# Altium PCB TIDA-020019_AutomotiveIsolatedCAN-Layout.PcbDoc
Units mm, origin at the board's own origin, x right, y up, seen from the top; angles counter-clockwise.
Board outline 60 x 40 mm, 2 copper layers (Top Layer, Bottom Layer), stack 1.575 mm thick; 61 components, 26 nets, 143 pads, 64 vias.
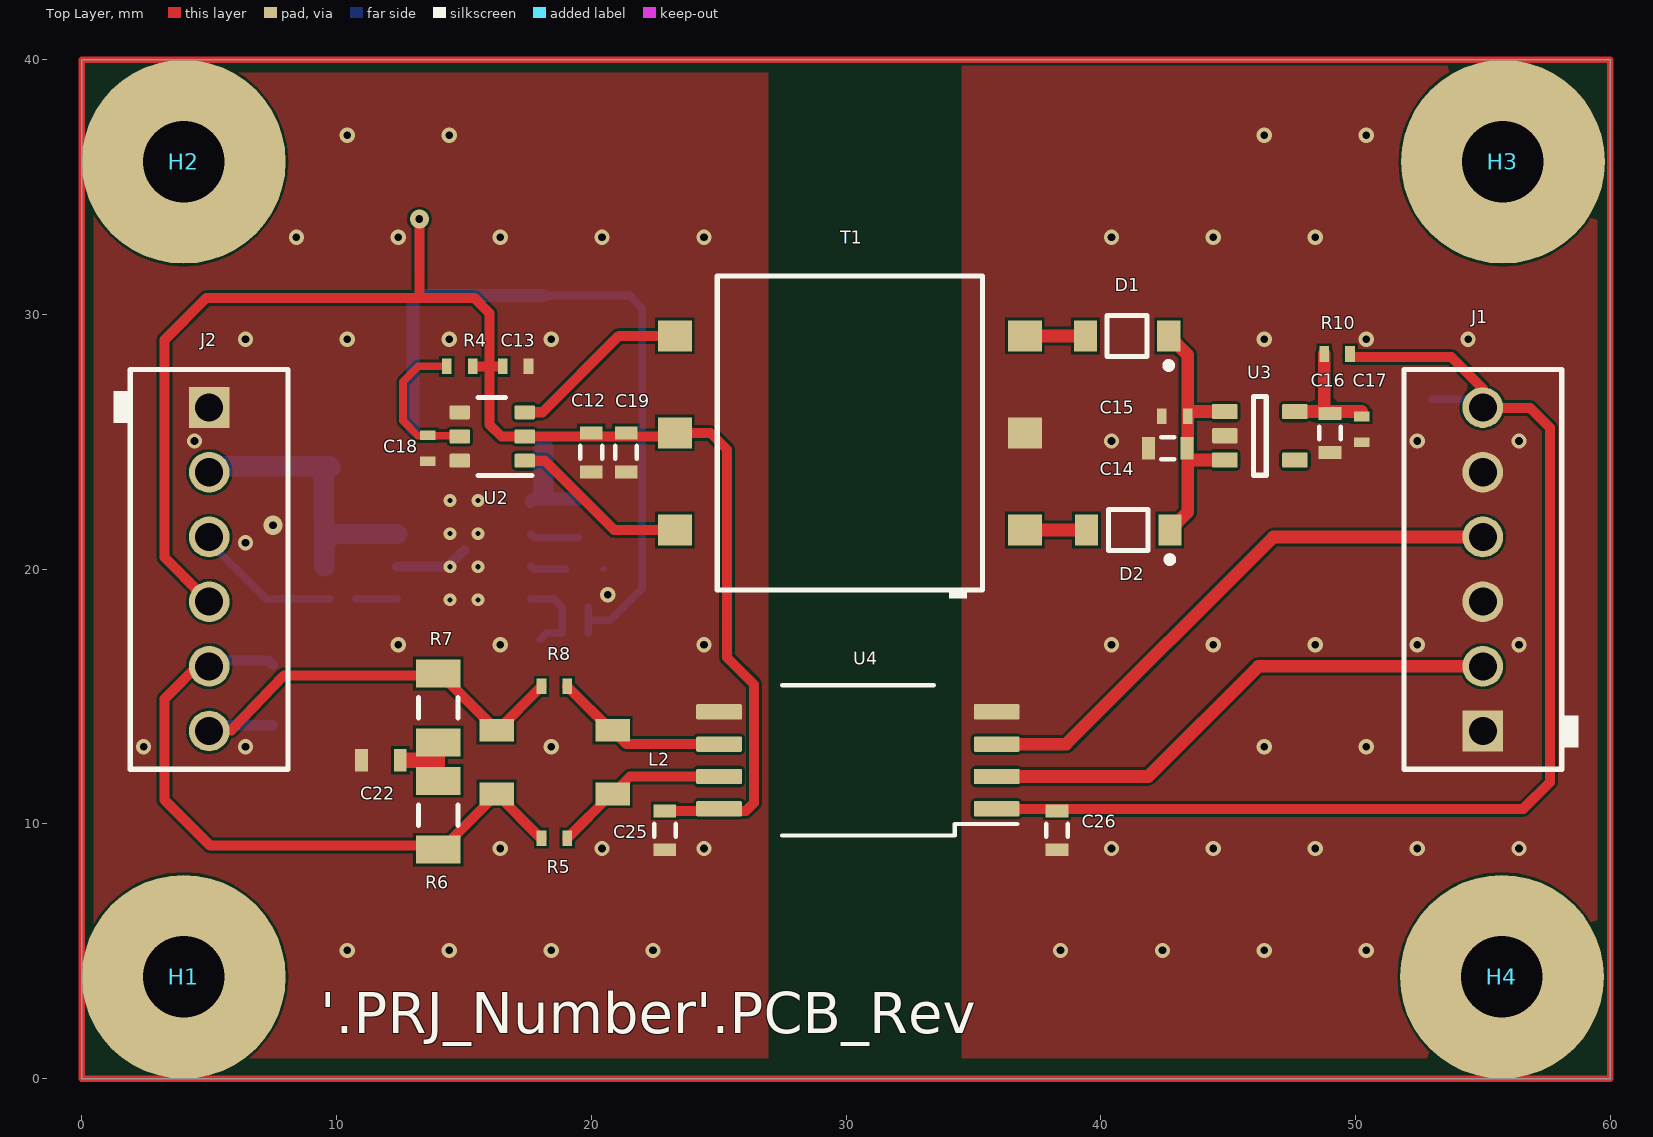
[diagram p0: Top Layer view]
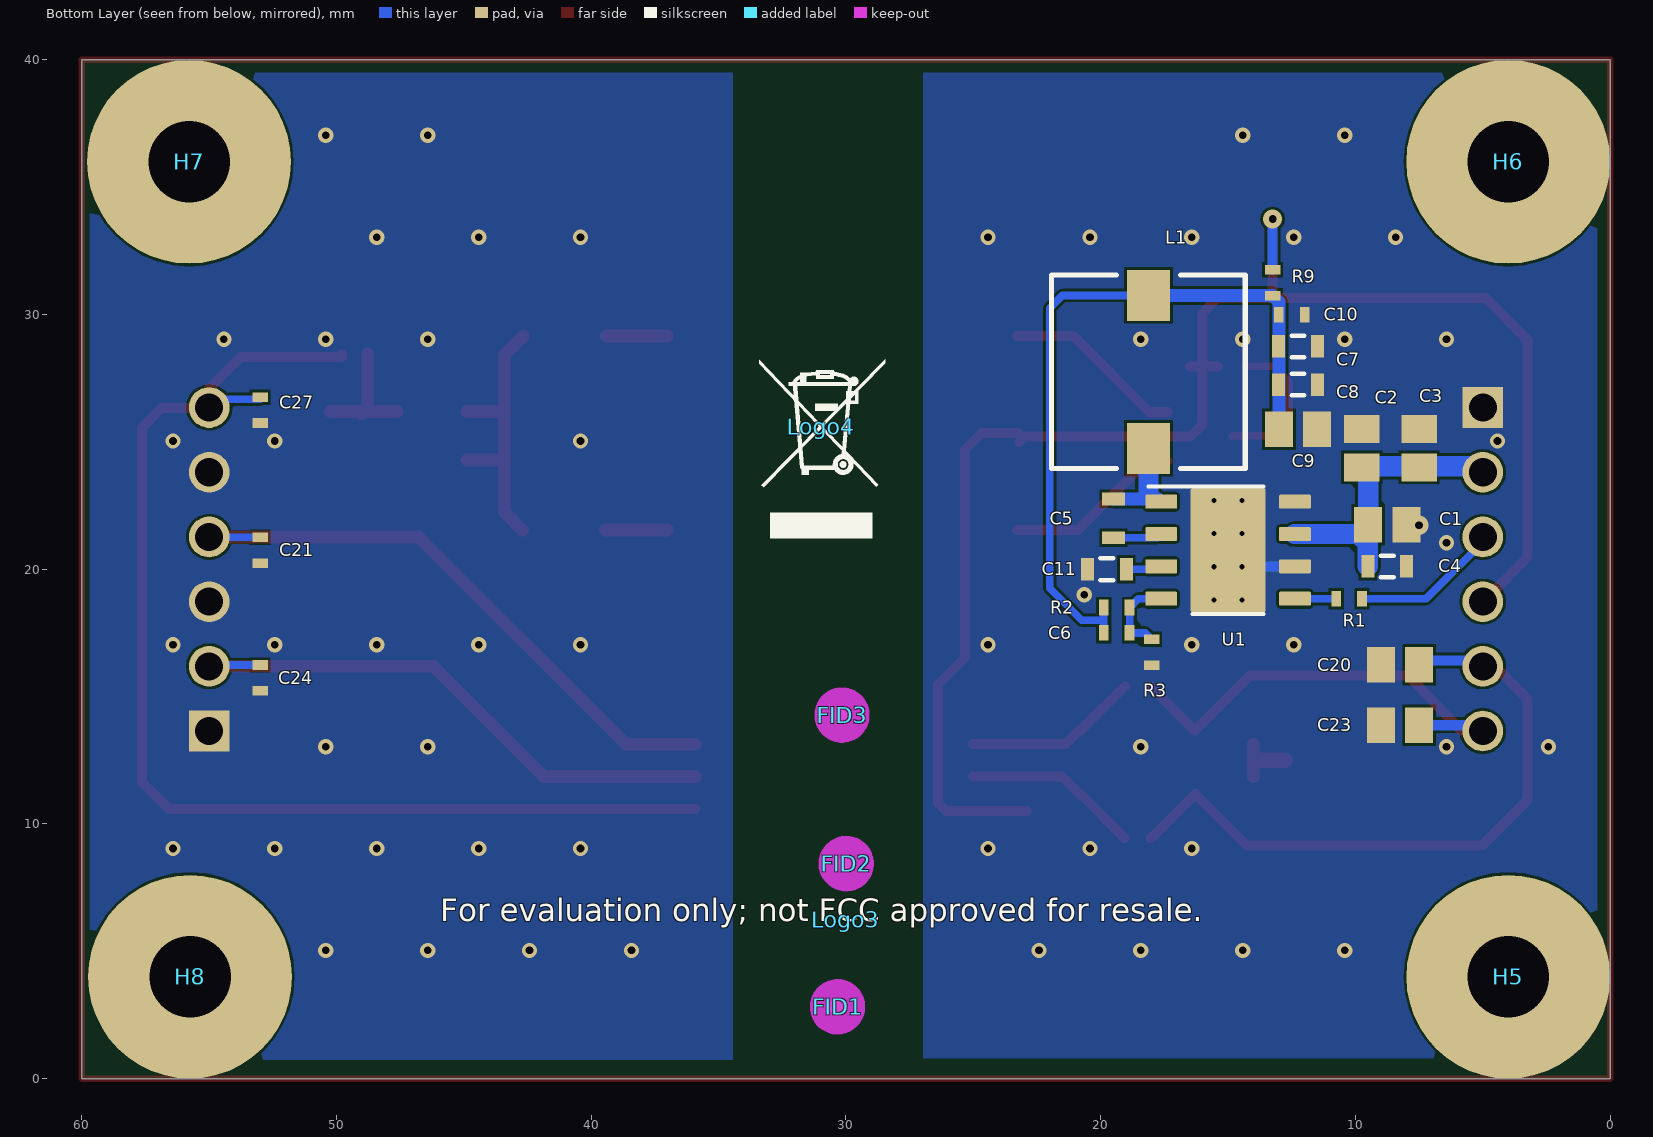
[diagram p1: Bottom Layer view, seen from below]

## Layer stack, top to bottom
Top Solder: solder mask 0.0102, Solder Resist, Dk 3.5
Top Layer: signal copper 0.0356
Dielectric1: core 1.5037, FR-4, Dk 4.8
Bottom Layer: signal copper 0.0356
Bottom Solder: solder mask 0.0102, Solder Resist, Dk 3.5

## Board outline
0,0 60,0 60,40 0,40

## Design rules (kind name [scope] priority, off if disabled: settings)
AcuteAngle [All] p1: minimum=4.50000000000000E+0001 checktracksonly=FALSE
AssemblyTestPointUsage [All] p1: valid=2
AssemblyTestpoint [All] p1: testpointundercomponent=TRUE minsize=1.016 maxsize=2.54 preferedsize=1.524 minholesize=0 maxholesize=1.016 preferedholesize=0.813 testpointgrid=0.025 usegrid=FALSE gridtolerance=0 allowsidetop=TRUE allowsidebottom=TRUE
BoardOutlineClearance BoardOutlineClearance_MountingHoles [OnCopper and InComponentClass('Mounting Holes')] p1: gap=0 ignorepadtopadclearanceinfootprint=FALSE
BoardOutlineClearance BoardOutlineClearance_Poly [OnCopper and IsPoly] p2: gap=0 ignorepadtopadclearanceinfootprint=FALSE
BoardOutlineClearance [OnCopper and Not InComponentClass('Logo') and not InComponentClass('FiducialMark') and not InRegion(1000,500,4000,800) and not InPoly] p3: gap=0 ignorepadtopadclearanceinfootprint=FALSE
Clearance Clearance_Keepouts [((IsTrack Or IsArc) And Not InPoly) And IsFree and IsKeepOut vs ((IsTrack Or IsArc) And Not InPoly) And IsFree and IsKeepOut] p1: gap=0 ignorepadtopadclearanceinfootprint=FALSE
Clearance Clearance_Poly [InPolygon] p2: gap=0.1 ignorepadtopadclearanceinfootprint=TRUE
Clearance Clearance_FiducialMark [IsKeepOut and InComponentClass('FiducialMark') vs IsPad and InComponentClass('FiducialMark')] p3: gap=0 ignorepadtopadclearanceinfootprint=FALSE
Clearance [All] p4: gap=0.2 ignorepadtopadclearanceinfootprint=TRUE
ComponentClearance ComponentClearance_MountingHoles_FiducialMarks [InComponentClass('Mounting Holes') vs InComponentClass('FiducialMark')] p1: gap=1.27 collisioncheckmode=3 verticalgap=0.254 showdistances=FALSE
ComponentClearance ComponentClearance_Shunt [InComponentClass('Header') vs InComponentClass('Shunt')] p2: gap=0 collisioncheckmode=3 verticalgap=0 showdistances=FALSE
ComponentClearance ComponentClearance_Logo [InComponentClass('Logo')] p3: gap=1.27 collisioncheckmode=3 verticalgap=0.254 showdistances=FALSE
ComponentClearance ComponentClearance_ScrewToNut [(HasFootprint('NY PMS 440 0025 PH')) vs (HasFootprint('Keystone_1902C'))] p4: gap=0.127 collisioncheckmode=3 verticalgap=0.1 showdistances=FALSE
ComponentClearance ComponentClearance_MountingHoles [InComponentClass('Mounting Holes')] p5: gap=0.5 collisioncheckmode=3 verticalgap=2540 showdistances=FALSE
ComponentClearance ComponentClearance_SmallPassives [HasFootprint('0201*') or HasFootprint('0402*') or HasFootprint('0508') or HasFootprint('0603*') or HasFootprint('0612') or HasFootprint('0805*') or HasFootprint('0815*') or HasFootprint('0830*') or HasFootprint('1206*') or HasFootprint('1210*') or HasFootprint('1808*') or HasFootprint('1812*') or HasFootprint('1825*') or HasFootprint('2010*') or HasFootprint('2220*') or HasFootprint('2225*') or HasFootprint('2512*') or HasFootprint('2728*') or HasFootprint('3518*') vs HasFootprint('0201*') or HasFootprint('0402*') or HasFootprint('0508') or HasFootprint('0603*') or HasFootprint('0612') or HasFootprint('0805*') or HasFootprint('0815*') or HasFootprint('0830*') or HasFootprint('1206*') or HasFootprint('1210*') or HasFootprint('1808*') or HasFootprint('1812*') or HasFootprint('1825*') or HasFootprint('2010*') or HasFootprint('2220*') or HasFootprint('2225*') or HasFootprint('2512*') or HasFootprint('2728*') or HasFootprint('3518*')] p6: gap=0.38 collisioncheckmode=3 verticalgap=0.254 showdistances=FALSE
ComponentClearance ComponentClearance_THtoSMT [IsThruComponent vs IsSMTComponent] p7: gap=1.016 collisioncheckmode=3 verticalgap=0.4 showdistances=FALSE
ComponentClearance ComponentClearance_THtoTH [IsThruComponent vs IsThruComponent] p8: gap=0.762 collisioncheckmode=3 verticalgap=0.5 showdistances=FALSE
ComponentClearance [All] p9: gap=0.1 collisioncheckmode=3 verticalgap=0.1 showdistances=FALSE
DiffPairsRouting [All] p1: maxlimit=2.54 minlimit=0.254 mostfreqgap=0.254 toplayer_minwidth=0.381 toplayer_maxwidth=0.381 toplayer_prefwidth=0.381 bottomlayer_minwidth=0.381 bottomlayer_maxwidth=0.381 bottomlayer_prefwidth=0.381 maxuncoupledlength=25.4
FabricationTestPointUsage TestPointUsage [All] p1: valid=2 allowmultiple=FALSE
FabricationTestpoint Testpoint [All] p1: side=3 testpointundercomponent=TRUE minsize=1.016 maxsize=2.54 preferedsize=1.524 minholesize=0 maxholesize=1.016 preferedholesize=0.813 testpointgrid=0.025 allowsidetop=TRUE allowsidebottom=TRUE usegrid=FALSE gridtolerance=0
FanoutControl Fanout_LCC [IsLCC] p1: bgadir=Out bgaviamode=Centered fanoutstyle=Auto fanoutdirection=Alternating viagrid=0.025 // Fanout_LCC (Default Rule)
FanoutControl Fanout_BGA [IsBGA] p2: bgadir=Out bgaviamode=Centered fanoutstyle=Auto fanoutdirection=Alternating viagrid=0.025 // Fanout_BGA (Default Rule)
FanoutControl Fanout_Default [All] p4: bgadir=Out bgaviamode=Centered fanoutstyle=Auto fanoutdirection=Alternating viagrid=0.025 // Fanout_Default (Default Rule)
FanoutControl Fanout_Small [(CompPinCount < 5)] p5: bgadir=Out bgaviamode=Centered fanoutstyle=Auto fanoutdirection=OutThenIn viagrid=0.025 // Fanout_Small (Default Rule)
HoleSize [All] p1: absolutevalues=TRUE maxlimit=6.375 minlimit=0.2 maxpercent=80.000 minpercent=20.000
MinimumAnnularRing MinimumAnnularRing_ThermalPadVias [IsVia and InAnyComponent] p1: minimumring=0.15
MinimumAnnularRing [All] p2: minimumring=0.15
MinimumSolderMaskSliver MinimumSolderMaskSliver_Logo [InComponentClass('Logo') vs InComponentClass('Logo')] p1: minsoldermaskwidth=0.018
MinimumSolderMaskSliver [All] p2: minsoldermaskwidth=0.1
PlaneConnect [All] p1: planeconnectstyle=Direct reliefexpansion=0.254 reliefentries=4 reliefconductorwidth=0.254 reliefairgap=0.254
PolygonConnect [All] p1: connectstyle=Direct reliefconductorwidth=0.254 reliefentries=4 polygonreliefangle="90 Angle" airgapwidth=0.254
RoutingVias ThermalPadVias [IsVia and InAnyComponent] p1: holewidth=0.2 width=0.5 viastyle="Through Hole" minholewidth=0.2 minwidth=0.5 maxholewidth=0.33 maxwidth=0.6
RoutingVias [All] p2: holewidth=0.406 width=0.864 viastyle="Through Hole" minholewidth=0.2 minwidth=0.59 maxholewidth=1.016 maxwidth=1.651
SilkToBoardRegionClearance [Not ((IsComment or IsDesignator) And (Hide <> 'False')) and not InRegion(1000,500,4000,800)] p1:
SilkToSilkClearance SilkToSilkClearance_Pb-FreeLogo [(HasFootprint('Pb-Free_Overlay_Medium') OR HasFootprint('Pb-Free_Overlay_Small')) vs (HasFootprint('Pb-Free_Overlay_Medium') OR HasFootprint('Pb-Free_Overlay_Small'))] p1: silktosilkclearance=0
SilkToSilkClearance [All] p2: silktosilkclearance=0.1
SilkToSolderMaskClearance SilkToComponentPadClearance [(IsPad or IsFill or IsRegion) and InAnycomponent] p1: minsilkscreentomaskgap=0.127 clearancetoexposedcopper=TRUE
SilkToSolderMaskClearance "Silk to Solder Mask Opening" [All] p2: minsilkscreentomaskgap=0 clearancetoexposedcopper=FALSE
SolderMaskExpansion [All] p1: expansion=0.05
UnRoutedNet [All] p1: checkbadconnections=TRUE
Width [All] p1: maxlimit=2.54 minlimit=0.152 preferedwidth=0.254 checkconnectedcopper=TRUE
13 further rules are at their usual default settings.

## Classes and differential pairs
component class "Mounting Holes": H1 H2 H3 H4
component class "TIDA-020019_Automotive IsolatedCAN-SCH-HW": FID1 FID2 FID3 H1 H2 H3 H4 H5 H6 H7 H8 Logo3 Logo4
component class FiducialMark: FID1 FID2 FID3
component class "TIDA-020019_Automotive IsolatedCAN-SCH-Page1": C1 C2 C3 C4 C5 C6 C7 C8 C9 C10 C11 C12 C13 C14 C15 C16 C17 C18 C19 C20 C21 C22 C23 C24 C25 C26 C27 D1 D2 J1 J2 L1 L2 R1 R2 R3 R4 R5 R6 R7 R8 R9 R10 T1 U1 U2 U3 U4

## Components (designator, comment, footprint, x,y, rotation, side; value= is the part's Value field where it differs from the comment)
C1 "GRT21BR61E226ME13L" 0805L 8.75,21.75 r180 bottom value=22uF
C2 "GRT21BR61H475KE13L" 0805L 9.75,24.75 r90 bottom value=4.7uF
C3 "GRT21BR61H475KE13L" 0805L 7.5,24.75 r90 bottom value=4.7uF
C4 "CGA3E2X7R1H104K080AA" 0603S 8.75,20.115 r180 bottom value=0.1uF
C5 "GCM188R71C104KA37J" 0603S 19.5,22 r270 bottom value=0.1uF
C6 "GRM1555C1H750JA01D" 0402S 19.375,17.5 r180 bottom value=75pF
C7 "GRT188C81A106ME13D" 0603S 12.25,28.75 r180 bottom value=10uF
C8 "GRT188C81A106ME13D" 0603S 12.25,27.25 r180 bottom value=10uF
C9 "GRT21BR61E226ME13L" 0805L 12.25,25.5 r180 bottom value=22uF
C10 "GCM155R71A104KA55D" 0402S 12.5,30 r180 bottom value=0.1uF
C11 "GRT188R61H225KE13D" 0603S 19.758,20 r0 bottom value=2.2uF
C12 "GRT188C81A106ME13D" 0603S 20,24.59 r270 top value=10uF
C13 "GCM155R71A104KA55D" 0402S 17.028,27.965 r0 top value=0.1uF
C14 "GRT188C81A106ME13D" 0603S 42.631,24.75 r180 top value=10uF
C15 "GCM155R71A104KA55D" 0402S 42.908,26 r180 top value=0.1uF
C16 "GRT188C81A106ME13D" 0603S 49,25.352 r270 top value=10uF
C17 "GCM155R71A104KA55D" 0402S 50.25,25.492 r270 top value=0.1uF
C18 "GCM155R71A104KA55D" 0402S 13.584,24.75 r270 top value=0.1uF
C19 "GRT188C81A106ME13D" 0603S 21.367,24.59 r270 top value=10uF
C20 "GQM2195C2AR50CB01D" 0805L 8.25,16.25 r0 bottom value=0.5pF
C21 "GRM1555C1HR10WA01D" 0402S 53,20.75 r90 bottom value=0.1pF
C22 "CGA3E2X7R2A472K080AA" 0603S 11.738,12.5 r180 top value=4700pF
C23 "GQM2195C2AR50CB01D" 0805L 8.25,13.88 r180 bottom value=0.5pF
C24 "GRM1555C1HR10WA01D" 0402S 53,15.736 r270 bottom value=0.1pF
C25 "GRT188C81A106ME13D" 0603S 22.891,9.75 r270 top value=10uF
C26 "GRT188C81A106ME13D" 0603S 38.282,9.75 r270 top value=10uF
C27 "GCM155R71A104KA55D" 0402S 53,26.25 r270 bottom value=0.1uF
D1 "MBR0520L" ONSC-SOD-123-2-425-04_V 41.033,29.162 r180 top
D2 "MBR0520L" ONSC-SOD-123-2-425-04_V 41.079,21.542 r180 top
FID1 "Fiducial" Fiducial6.4-20 30.333,2.82 r180 bottom
FID2 "Fiducial" Fiducial6.4-20 29.992,8.445 r180 bottom
FID3 "Fiducial" Fiducial6.4-20 30.157,14.278 r180 bottom
H1 "NY PMS 440 0025 PH" "NY PMS 440 0025 PH" 4,4 r0 top locked
H2 "NY PMS 440 0025 PH" "NY PMS 440 0025 PH" 4,36 r0 top locked
H3 "NY PMS 440 0025 PH" "NY PMS 440 0025 PH" 55.79,36 r0 top locked
H4 "NY PMS 440 0025 PH" "NY PMS 440 0025 PH" 55.75,4 r0 top locked
H5 "1902C" Keystone_1902C 4,4 r180 bottom locked
H6 "1902C" Keystone_1902C 4,36 r180 bottom locked
H7 "1902C" Keystone_1902C 55.79,36 r180 bottom locked
H8 "1902C" Keystone_1902C 55.75,4 r180 bottom locked
J1 "1725698" Phoenix_1725698 55,20 r90 top
J2 "1725698" Phoenix_1725698 5,20 r270 top
L1 "7447779122" WE-PD_7345_PlasticBase 18.125,27.75 r90 bottom value=22uH
L2 "ACT45B-101-2P-TL003" ACT45B_NoSilk 18.56,12.43 r180 top value=100uH
Logo3 "FCC disclaimer" FCC_disclaimer 30,6.25 r180 bottom
Logo4 "WEEE logo" WEEE_Minimum 30.979,25.596 r180 bottom
R1 "ERJ-2GEJ203X" 0402S 10.25,18.845 r180 bottom value=20k
R2 "CRCW040280K6FKED" 0402S 19.375,18.5 r0 bottom value=80.6k
R3 "ERJ-2GEJ203X" 0402S 18,16.742 r90 bottom value=20k
R4 "ERJ-2GEJ203X" 0402S 14.838,27.965 r0 top value=20k
R5 "CRCW04020000Z0ED" 0402S 18.55,9.445 r0 top value=0
R6 "ERJ-8ENF60R4V" 1206L 13.989,10.346 r270 top value=60.4
R7 "ERJ-8ENF60R4V" 1206L 13.989,14.558 r270 top value=60.4
R8 "CRCW04020000Z0ED" 0402S 18.55,15.4 r0 top value=0
R9 "CRCW04020000Z0ED" 0402S 13.25,31.25 r90 bottom value=0
R10 "CRCW04020000Z0ED" 0402S 49.283,28.452 r0 top value=0
T1 "750315240" Wurth_750315240 30.148,25.352 r180 top value=110uH
U1 "LMR23610AQDDARQ1" DDA0008E_L 15,20.75 r180 bottom
U2 "SN6505ADBVR" DBV0006A_L 16.113,25.215 r180 top
U3 "TPS76350QDBVRQ1" DBV0005A_N 46.25,25.241 r0 top
U4 "ISO1042BDWV" DWV0008A 30.467,12.5 r180 top

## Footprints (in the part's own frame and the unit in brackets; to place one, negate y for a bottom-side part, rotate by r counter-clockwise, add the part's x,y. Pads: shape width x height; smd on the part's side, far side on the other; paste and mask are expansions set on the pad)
0402S [mil] "Based on C0402S footprint from PADS legacy"
  rect 15x24 smd: 1(-20,0) 2(20,0)
  body extent -22,-12 22,12, height 24
0603S [mil]
  rect 20x35 smd: 1(-30,0) 2(30,0)
  silkscreen extent -10,-17 10,17, body extent -34,-19 34,19, height 39
0805L [mm] "0805 from SM-752 data"
  rect 1.1x1.4 smd: 1(-0.75,0) 2(0.75,0)
  body extent -1.1,-0.72 1.1,0.72, height 1.45
1206L [mm] "1206 from SM-752 data"
  rect 1.1x1.75 smd: 1(-1.35,0) 2(1.35,0)
  silkscreen extent -0.4,-0.77 0.4,0.77, body extent -1.7,-0.9 1.7,0.9, height 1.35
ACT45B_NoSilk [mm] "SMD, 4-Leads, Body 4.7 x 3.7 mm"
  rect 1.35x0.9 smd: 1(-2.275,1.25) 2(-2.275,-1.25) 3(2.275,-1.25) 4(2.275,1.25)
  body extent -2.35,-1.7 2.35,1.7, height 3
DBV0005A_N [mm] "SOT23, 5-Leads, Body 2.9x1.6mm, Pitch 0.95mm, Lead Span 2.8mm, IPC Medium Density"
  rrect17% 1x0.6 smd: 1(-1.375,0.95) 2(-1.375,0) 3(-1.375,-0.95) 4(1.375,-0.95) 5(1.375,0.95)
  silkscreen extent -0.25,-1.55 0.25,1.55, body extent -1.42,-1.46 1.42,1.46, height 1.09
DBV0006A_L [mm] "SOT23, 6-Leads, Body 2.9x1.6mm, Pitch 0.95mm, Lead Span 2.8mm, IPC High Density"
  rrect18% 0.8x0.55 smd: 1(-1.275,0.95) 2(-1.275,0) 3(-1.275,-0.95) 4(1.275,-0.95) 5(1.275,0) 6(1.275,0.95)
  silkscreen extent -1.55,-1.53 0.55,1.53, body extent -1.42,-1.46 1.42,1.46, height 1.12
DDA0008E_L [mm]
  rrect18% 1.25x0.55 smd: 1(-2.625,1.905) 2(-2.625,0.635) 3(-2.625,-0.635) 4(-2.625,-1.905) 5(2.625,-1.905) 6(2.625,-0.635) 7(2.625,0.635) 8(2.625,1.905)
  rrect7% 2.95x4.9 smd paste-1.5 mask-1.5: 9(0,0)
  rrect4% 2.4x3.1 on Bottom Paste: 9(0,0)
  rrect4% 2.4x3.1 on Bottom Solder: 9(0,0)
  silkscreen extent -3.13,-2.5 1.4,2.5, body extent -3,-2.45 3,2.45, height 1.57
DWV0008A [mm] "SOIC, 8-Leads, Body 5.95x7.6mm (max), Pitch 1.27mm"
  rrect17% 1.8x0.6 smd: 1(-5.45,1.905) 2(-5.45,0.635) 3(-5.45,-0.635) 4(-5.45,-1.905) 5(5.45,-1.905) 6(5.45,-0.635) 7(5.45,0.635) 8(5.45,1.905)
  silkscreen extent -6.25,-2.95 2.98,2.95, body extent -5.77,-2.92 5.77,2.93, height 2.67
FCC_disclaimer [mm]
Fiducial6.4-20 [mm]
  round 0.635 smd mask+0.683: 1(0,0)
  Top Layer keep-out circle w1.178: c0,0 r0.5
Keystone_1902C [mil] "Hex Standoff, 4-40 threaded, nylon"
  round 1 on Mech4: 0(0,0)
  body extent -145,-126 146,126, height 501
"NY PMS 440 0025 PH" [mm] "4-40 nylon screw and mounting hole"
  round 8 hole 3.2: 1(0,0)
  body extent -3.3,-3.3 3.3,3.3, height 2.69
ONSC-SOD-123-2-425-04_V [mm] "SOD, 2-Leads, Body 2.69x1.6mm"
  rect 0.91x1.22 smd: 1(-1.635,0) 2(1.635,0)
  silkscreen extent -1.76,-0.8 0.78,1.28, body extent -1.35,-0.8 1.35,0.8, height 1.35
Phoenix_1725698 [mm] "Terminal Block, 6x1, 2.54mm, TH"
  rect 1.6x1.6 hole 1.1: 1(-6.35,0)
  round 1.6 hole 1.1: 2(-3.81,0) 3(-1.27,0) 4(1.27,0) 5(3.81,0) 6(6.35,0)
  silkscreen extent -7.85,-3.75 7.85,3.1, body extent -7.85,-3.1 7.85,3.1, height 8.51
WE-PD_7345_PlasticBase [mm] "SMD Inductor, 2-Leads, Body 7,3x7,3mm"
  rect 2x1.7 smd: 1(-3,0) 2(3,0)
  silkscreen extent -3.8,-3.8 3.8,3.8, body extent -3.65,-3.65 3.65,3.65, height 4.09
WEEE_Minimum [mm] "WEEElie bin"
  silkscreen extent -2.42,-4.38 2.52,2.65
Wurth_750315240 [mm] "SMD, 6-Leads, Body 10.41x12.32mm"
  rect 1.335x1.215 smd: 1(-6.87,3.81) 2(-6.87,0) 3(-6.87,-3.81) 4(6.87,-3.81) 5(6.87,0) 6(6.87,3.81)
  silkscreen extent -5.21,-6.16 5.21,6.5, body extent -7.43,-6.16 7.43,6.16, height 11.06

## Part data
C1 C9: library part CMP-0084680-1, "CAP, CERM, 22 µF, 25 V,+/- 20%, X5R, AEC-Q200 Grade 3, 0805", Cap_Case=0805, Manufacturer=MuRata, TempCo=X5R, Tolerance_%=20%, Value2=25V, ValueDisplayed=22µF
C2 C3: library part CMP-0008380-1, "CAP, CERM, 4.7 uF, 50 V, +/- 10%, X5R, AEC-Q200 Grade 3, 0805", Cap_Case=0805, Manufacturer=MuRata, Supplier Part Number 1=490-12394-1-ND, TempCo=X5R, Tolerance_%=10%, Value1=Unknown, Value2=50V, ValueDisplayed=4.7uF
C4: library part CMP-0007078-1, "CAP, CERM, 0.1 uF, 50 V, +/- 10%, X7R, AEC-Q200 Grade 1, 0603", Cap_Case=0603, Manufacturer=TDK, Supplier Part Number 1=445-5666-1-ND, TempCo=X7R, Tolerance_%=10%, Value1="0.0296 ohm", Value2=50V, ValueDisplayed=0.1uF
C5: library part CMP-0007135-4, "CAP, CERM, 0.1 uF, 16 V, +/- 10%, X7R, AEC-Q200 Grade 1, 0603", Cap_Case=0603, Manufacturer=MuRata, Supplier Part Number 1=490-8015-1-ND, TempCo=X7R, Tolerance_%=10%, Value1=Unknown, Value2=16V, ValueDisplayed=0.1uF
C6: library part CMP-0006489-1, "CAP, CERM, 75 pF, 50 V, +/- 5%, C0G/NP0, 0402", Cap_Case=0402, Manufacturer=MuRata, Supplier Part Number 1=81-GRM1555C1H750JA1D, TempCo=C0G/NP0, Tolerance_%=5%, Value1=Unknown, Value2=50V, ValueDisplayed=75pF
C7 C8 C12 C14 C16 C19 C25 C26: library part CMP-0007500-1, "CAP, CERM, 10 uF, 10 V, +/- 20%, X6S, AEC-Q200 Grade 2, 0603", Cap_Case=0603, Manufacturer=MuRata, Supplier Part Number 1=490-12283-1-ND, TempCo=X6S, Tolerance_%=20%, Value1=Unknown, Value2=10V, ValueDisplayed=10uF
C10 C13 C15 C17 C18 C27: library part CMP-0006350-1, "CAP, CERM, 0.1 uF, 10 V, +/- 10%, X7R, AEC-Q200 Grade 1, 0402", Cap_Case=0402, Manufacturer=MuRata, Supplier Part Number 1=81-GCM155R71A104K5D, TempCo=X7R, Tolerance_%=10%, Value1=Unknown, Value2=10V, ValueDisplayed=0.1uF
C11: library part CMP-0007502-1, "CAP, CERM, 2.2 uF, 50 V, +/- 10%, X5R, AEC-Q200 Grade 3, 0603", Cap_Case=0603, Manufacturer=MuRata, Supplier Part Number 1=490-12332-1-ND, TempCo=X5R, Tolerance_%=10%, Value1=Unknown, Value2=50V, ValueDisplayed=2.2uF
C20 C23: library part CMP-0008057-1, "CAP, CERM, 0.5 pF, 100 V, +/- 5%, C0G/NP0, 0805", Cap_Case=0805, Manufacturer=MuRata, Supplier Part Number 1=490-3584-1-ND, TempCo=C0G/NP0, Tolerance_%=5%, Value1=Unknown, Value2=100V, ValueDisplayed=0.5pF
C21 C24: library part CMP-0006499-2, "CAP, CERM, 0.1pF, 50 V, +/- 50%, C0G/NP0, 0402", Cap_Case=0402, Manufacturer=MuRata, Supplier Part Number 1=490-6259-1-ND, TempCo=C0G/NP0, Tolerance_%=50%, Value1=Unknown, Value2=50V, ValueDisplayed=0.1pF
C22: library part CMP-0007088-4, "CAP, CERM, 4700 pF, 100 V, +/- 10%, X7R, AEC-Q200 Grade 1, 0603", Cap_Case=0603, Manufacturer=TDK, Supplier Part Number 1=445-5810-1-ND, TempCo=X7R, Tolerance_%=10%, Value1="0.469862 ohm", Value2=100V, ValueDisplayed=4700pF
D1 D2: library part CMP-2000-04926-1, "Schottky Diode, 20V, 0.2A, 2-pin SOD-123, RoHS, Tape and Reel", Manufacturer=FairchildSemiconductor, Operating Temperature=-65to125degC, Package=2SOD-123, Package Description="2-Pin Small Outline Diode, Body 2.69 x 1.6 mm", Package Reference=SOD-123-2-425-04, Peak Average Forward Current=0.5A, Peak Forward Voltage=0.385V, Peak Non-Repetitive Surge Current=5.5A, Peak Reverse Current=250uA, Peak Reverse Repetitive Voltage=20V
FID1 FID2 FID3: library part CMP-0077181-1, "Fiducial mark.  There is nothing to buy or mount.", Manufacturer=N/A
H1 H2 H3 H4: library part CMP-0003617-1, "Machine Screw, Round, #4-40 x 1/4, Nylon, Philips panhead", Manufacturer="B&F Fastener Supply", Supplier Part Number 1=H542-ND
H5 H6 H7 H8: library part CMP-0003610-1, "Standoff, Hex, 0.5\"L #4-40 Nylon", Manufacturer=Keystone, Supplier Part Number 1=36-1902C-ND
J1 J2: library part CMP-0055512-1, "Terminal Block, 6x1, 2.54mm, TH", Color=Green, Current_A=6A, Manufacturer="Phoenix Contact", Supplier Part Number 1=277-1277-ND, Voltage_V=160V
L1: library part CMP-0064637-2, "Inductor, Shielded Drum Core, Ferrite, 22 uH, 1.41 A, 0.09 ohm, SMD", Manufacturer="Wurth Elektronik", Supplier Part Number 1=732-1194-1-ND, Value1="0.09 ohm", Value2=1.41A, ValueDisplayed=22uH
L2: library part CMP-0062430-2, "Inductor, Ferrite, 100 uH, 0.15 A, 2 ohm, SMD", Manufacturer=TDK, Supplier Part Number 1=445-3959-1-ND, Value1="2 ohm", Value2=0.15A, ValueDisplayed=100uH
Logo3: library part CMP-0074847-1, "FCC_disclaimer"
Logo4: library part CMP-0074769-1
R1 R3 R4: library part CMP-0026996-1, "RES, 20 k, 5%, 0.1 W, AEC-Q200 Grade 0, 0402", Manufacturer=Panasonic, Power_W=100mW, Supplier Part Number 1=P20KJCT-ND, TempCo="200 ppm/C", Tolerance_%=5%, Value2=0.1W, Value_Code=20k0, ValueDisplayed=20k
R2: library part CMP-0026570-1, "RES, 80.6 k, 1%, 0.063 W, 0402", Manufacturer=Vishay-Dale, Power_W=63mW, Supplier Part Number 1=541-80.6KLCT-ND, TempCo="100 ppm/C", Tolerance_%=1%, Value2=0.063W, Value_Code=80k6, ValueDisplayed=80.6k
R5 R8 R9 R10: library part CMP-0026822-3, "RES, 0, 5%, 0.063 W, AEC-Q200 Grade 0, 0402", Manufacturer=Vishay-Dale, Power_W=63mW, Supplier Part Number 1=541-0.0JCT-ND, TempCo="200 ppm/C", Tolerance_%=5%, Value2=0.063W, Value_Code=0000, ValueDisplayed=0
R6 R7: library part CMP-0017672-3, "RES, 60.4, 1%, 0.25 W, AEC-Q200 Grade 0, 1206", Manufacturer=Panasonic, Power_W=250mW, Supplier Part Number 1=P60.4FCT-ND, TempCo="100 ppm/C", Tolerance_%=1%, Value2=0.25W, Value_Code=60R4, ValueDisplayed=60.4
T1: library part CMP-0030614-1, "Transformer, 110 uH, SMT", Manufacturer="Wurth Elektronik", ValueDisplayed=110uH
U1: library part CMP-0013265-3, "SIMPLE SWITCHER, 36V, 1A Synchronous Step-Down Converter, DDA0008E (SOIC-8)", Alternate Manufacturer="Texas Instruments", Alternate PartNumber=LMR23610AQDDAQ1
U2: library part CMP-0076094-1, "Low-Noise 1-A Transformer Driver for Isolated Power Supplies, Internal Clock-160kHz, DBV0006A (SOT-23-6)", Alternate Manufacturer="Texas Instruments", Alternate PartNumber=SN6505ADBVT
U3: library part CMP-0035574-1, "Single Output Automotive LDO, 150 mA, Fixed 5 V Output, 2.7 to 10 V Input, 5-pin SOT-23 (DBV), -40 to 125 degC, Green (RoHS & no Sb/Br)", Manufacturer="Texas Instruments"
U4: library part CMP-0077951-1, "Reinforced Isolated CAN XCVRs with 70V Protection Voltage and CAN FD, DWV0008A (SOIC-8)", Alternate Manufacturer="Texas Instruments", Alternate PartNumber=ISO1042BDWVR

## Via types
v1: diameter 0.6, hole 0.3, Top Layer to Bottom Layer, 54 vias
v2: diameter 0.5, hole 0.2, Top Layer to Bottom Layer, tented both sides, 4 vias
v3: diameter 0.5, hole 0.2, Top Layer to Bottom Layer, 4 vias
v4: diameter 0.75, hole 0.3, Top Layer to Bottom Layer, 2 vias

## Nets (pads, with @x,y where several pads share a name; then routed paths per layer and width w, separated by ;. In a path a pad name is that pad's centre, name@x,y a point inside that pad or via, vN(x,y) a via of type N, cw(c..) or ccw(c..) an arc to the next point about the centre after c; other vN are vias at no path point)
BATT12V: C1.1 C2.1 C3.1 C4.1 J2.2 U1.7 | length 11.3
  Bottom Layer w0.8: J2.2@4.75,24.04 9.71,24.04 C2.1 ; C2.1@9.5,23.75 C4.1 ; C1.1@9.75,21.25 9.885,21.385 U1.7
"CAN High": C20.1 J2.5 L2.4 R5.1 R6.2 | length 26.3
  Top Layer w0.4: J2.5@4.75,16.42 3.25,14.92 3.25,10.939 5.039,9.15 14,9.15 14.255,9.15 L2.4 18.02,9.445 R5.1
  Bottom Layer w0.3: J2.5@4.75,16.42 J2.5@4.92,16.25
  Bottom Layer w0.4: J2.5@4.75,16.42 7.33,16.42 C20.1
"CAN Low": C23.2 J2.6 L2.3 R7.1 R8.1 | length 18.3
  Top Layer w0.4: J2.6 5.867,13.68 7.935,15.835 14,15.835 14.13,15.835 L2.3 16.322,13.68 R8.1
  Bottom Layer w0.4: J2.6@4.75,13.88 C23.2
"CAN RX": C21.2 J1.4 U4.3 | length 24.5
  Top Layer w0.5: U4.3 38.644,13.135 46.779,21.27 J1.4
  Bottom Layer w0.3: C21.2 54.988,21.258 J1.4
"CAN TX": C24.1 J1.2 U4.2 | length 22.9
  Top Layer w0.5: U4.2 41.865,11.865 46.19,16.19 J1.2
  Bottom Layer w0.3: C24.1 54.946,16.244 J1.2
GND: C1.2 C2.2 C3.2 C4.2 C7.2 C8.2 C9.2 C10.2 C11.2 C12.2 C13.2 C18.2 C19.2 C20.2 C22.2 C23.1 C25.2 J2.1 R3.1 U1.6 U1.8 U1.9@15,20.75 U2.4 U2.6 U4.5 | length 2.9
  Bottom Layer w0.2: C11.2@20.463,20 C11.2
  Bottom Layer w0.4: U1.6 14.365,20.115 U1.9@15,20.75
  other v1: 10.423,5.036 14.423,5.036 18.423,5.036 22.423,5.036 16.423,9.036 20.423,9.036 24.423,9.036 2.423,13.036 6.423,13.036 18.423,13.036 12.423,17.036 16.423,17.036 24.423,17.036 20.644,19 6.423,21.036 4.423,25.036 6.423,29.036 10.423,29.036 14.423,29.036 18.423,29.036 8.423,33.036 12.423,33.036 16.423,33.036 20.423,33.036 24.423,33.036 10.423,37.036 14.423,37.036
  other v2: 14.45,18.8 15.55,18.8 14.45,22.7 15.55,22.7
  other v3: 14.45,20.1 15.55,20.1 14.45,21.4 15.55,21.4
  other v4: 7.502,21.728
GNDi: C14.2 C15.2 C16.2 C17.2 C21.1 C24.2 C26.2 C27.2 J1.1 J1.3 J1.5 T1.2 U3.2 U4.4
  other v1: 38.423,5.036 42.423,5.036 46.423,5.036 50.423,5.036 40.423,9.036 44.423,9.036 48.423,9.036 52.423,9.036 56.423,9.036 46.423,13.036 50.423,13.036 40.423,17.036 44.423,17.036 48.423,17.036 52.423,17.036 56.423,17.036 40.423,25.036 52.423,25.036 56.423,25.036 46.423,29.036 50.423,29.036 54.423,29.036 40.423,33.036 44.423,33.036 48.423,33.036 46.423,37.036 50.423,37.036
KL15: J2.3 R1.2 | length 6.2
  Bottom Layer w0.3: J2.3@4.75,21.5 4.75,21.325 7.23,18.845 R1.2
NetC5_1: C5.1 L1.1 U1.1 | length 3.7
  Bottom Layer w0.5: U1.1 17.732,22.762 C5.1
  Bottom Layer w0.8: 18.125,23 L1.1
NetC5_2: C5.2 U1.2 | length 1.9
  Bottom Layer w0.3: U1.2 17.772,21.238 C5.2
NetC6_2: C6.2 R2.1 R3.2 U1.4 | length 3.4
  Bottom Layer w0.3: U1.4 18.522,18.845 R2.1 C6.2 18.25,17.5 R3.2
NetC11_1: C11.1 U1.3 | length 1.4
  Bottom Layer w0.3: U1.3 17.74,20 C11.1
NetC14_1: C14.1 C15.1 D1.1 D2.1 U3.1 U3.3 | length 11.2
  Top Layer w0.5: D1.1 43.416,28.415 C15.1 ; D2.1 43.416,22.243 43.416,24.25 ; U3.3 43.456,24.291 43.416,24.25 ; U3.1 43.606,26.191 C15.1 ; 43.416,24.25 C15.1
NetC18_1: C18.1 R4.1 U2.5 | length 6
  Top Layer w0.3: R4.1 13.215,27.965 12.608,27.358 12.608,25.829 13.195,25.242 13.584,25.242 14.811,25.242 U2.5
NetC22_1: C22.1 R6.1 R7.2 | length 2.4
  Top Layer w0.5: R6.1@14,11.85 14,12.5 R7.2@14,13.135
  Top Layer w0.6: C22.1@12.75,12.5 13.9,12.5
NetD1_2: D1.2 T1.3 | length 2.4
  Top Layer w0.5: T1.3 D1.2
NetD2_2: D2.2 T1.1 | length 2.4
  Top Layer w0.5: T1.1 D2.2
NetL2_1: L2.1 R5.2 U4.7 | length 7
  Top Layer w0.4: R5.2 20.793,11.18 L2.1 21.52,11.865 U4.7
NetL2_2: L2.2 R8.2 U4.6 | length 6.9
  Top Layer w0.4: R8.2 20.778,13.68 L2.2 21.38,13.135 U4.6
NetR1_1: R1.1 U1.5 | length 1.6
  Bottom Layer w0.3: R1.1 U1.5
NetT1_4: T1.4 U2.3 | length 7.1
  Top Layer w0.4: U2.3 18.085,26.165 21.082,29.162 T1.4
NetT1_6: T1.6 U2.1 | length 7
  Top Layer w0.4: U2.1 18.181,24.265 20.904,21.542 T1.6
VCC5V: C12.1 C13.1 C19.1 C25.1 J2.4 R4.2 R9.2 T1.5 U2.2 U4.8 | length 62.7
  Top Layer w0.4: J2.4@4.75,18.96 3.25,20.46 3.25,29.011 4.896,30.656 13.25,30.656 ; v4(13.25,33.75) 13.25,30.656 ; R4.2@15.397,27.965 15.885,27.965 16,28.08 ; C13.1@16.483,27.965 16.115,27.965 16,28.08 ; C25.1 26.067,10.512 26.39,10.835 26.39,15.478 25.328,16.539 25.328,24.702 24.678,25.352 T1.5 ; T1.5@23.195,25 22.98,25.215 U2.2 16.472,25.215 16,25.687 16,28.08 ; 13.25,30.656 15.404,30.656 16,30.061 16,28.08
  Bottom Layer w0.4: R9.2 v4(13.25,33.75)
VCC5V_1: C6.1 C7.1 C8.1 C9.1 C10.1 L1.2 R2.2 R9.1 | length 28.9
  Bottom Layer w0.3: L1.2 21.5,30.75 22,30.25 22,19.25 20.75,18 19.883,18 ; C6.1 19.883,18 ; R2.2 19.883,18
  Bottom Layer w0.5: C9.1 13,30.492 R9.1 13.258,30.75 L1.2
VCC5V_ISO: C16.1 C17.1 R10.1 U3.5 | length 5.1
  Top Layer w0.5: U3.5 C16.1@48.923,26.191 ; R10.1 48.775,26.339 C16.1@48.923,26.191 ; C16.1 C16.1@48.923,26.191 ; 50.25,26.192 49,26.191 C16.1@48.923,26.191
VCC_CAN: C26.1 C27.1 J1.6 R10.2 U4.1 | length 47
  Top Layer w0.4: U4.1 56.595,10.595 57.638,11.638 57.638,25.554 56.862,26.33 J1.6@55.75,26.33 ; R10.2 49.791,28.336 53.764,28.336 55,27.1 J1.6
  Bottom Layer w0.3: C27.1@53,26.68 54.67,26.68 J1.6
pads on no net: FID1.1 FID2.1 FID3.1 H1.1 H2.1 H3.1 H4.1 H5.0 H6.0 H7.0 H8.0 U1.9@15,20.75 U3.4
copper on no net: | length 200
  Top Layer w0.254: 0,0 0,40 60,40 60,0 0,0

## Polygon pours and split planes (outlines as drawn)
GNDi on Top Layer "TOP_LAYER_GNDI_P002" (solid, remove dead copper, pour order 2): 34.543,0.812 34.543,40 59.5,40 59.5,0.812
GND on Top Layer "TOP_LAYER_GND_P000" (solid, remove dead copper, pour order 0): 0.473,39.5 26.945,39.5 26.945,0.812 0.473,0.812
GNDi on Bottom Layer "BOTTOM_LAYER_GNDI_P010" (solid, pour order 10): 34.44,39.5 34.44,0.75 59.75,0.75 59.75,39.25 60,39.5
no net on Bottom Layer "BOTTOM_LAYER_NONET_P008" (solid, remove dead copper, pour order 8): 19.883,11.5
no net on Bottom Layer "BOTTOM_LAYER_NONET_P006" (solid, remove dead copper, pour order 6): 20.75,11
GND on Bottom Layer "BOTTOM_LAYER_GND_P004" (solid, remove dead copper, pour order 4): 26.972,0.812 0.5,0.812 0.5,39.5 26.972,39.5

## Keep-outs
Keep-Out Layer:
  text ".Layer_Name" at 14.656,-21.806 h1.52

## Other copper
Top Layer:
  text ".Layer_Name" at 14.656,-21.806 h1.52
Bottom Layer:
  text ".Layer_Name" at 14.656,-21.806 h1.52

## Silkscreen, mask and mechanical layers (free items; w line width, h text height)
Top Overlay:
  text "'.PRJ_Number'.PCB_Rev" at 9.35,1.25 h2.75
  text ".Layer_Name" at 14.656,-21.806 h1.52
Bottom Overlay:
  text ".Layer_Name" at 14.656,-21.806 h1.52
Top Paste:
  text ".Layer_Name" at 14.656,-21.806 h1.52
Bottom Paste:
  text ".Layer_Name" at 14.656,-21.806 h1.52
Top Solder:
  text ".Layer_Name" at 14.656,-21.806 h1.52
  text ".Layer_Name" at 14.656,-21.806 h1.52
Bottom Solder:
  text ".Layer_Name" at 14.656,-21.806 h1.52
Drill Guide:
  text ".Layer_Name" at 14.656,-21.806 h1.52
M1 Board Outline:
  text ".Layer_Name" at 14.656,-21.806 h1.52
M2 Board Dimensions:
  rectangle: 0,-6.985 3.175,-3.81
  rectangle: 3.175,-10.16 12.7,-6.985
  lines w0.178: 0,-6.985 25.4,-6.985 ; 3.175,-10.16 3.175,-3.81 ; 6.35,-10.16 6.35,-3.81 ; 12.7,-10.16 12.7,-3.81 ; 19.05,-10.16 19.05,-3.81 ; 0,-10.16 25.4,-10.16 25.4,-3.81 0,-3.81 0,-10.16
  text ".Layer_Name" at 14.656,-21.806 h1.52
M3 3D STEP Top:
  text ".Layer_Name" at 14.656,-21.806 h1.52
M4 3D STEP Bottom:
  text ".Layer_Name" at 14.656,-21.806 h1.52
M5 Assembly Top:
  lines w0.254: -7.417,-23.626 160.223,-23.626 ; -7.417,-18.462 160.274,-18.462 ; -7.417,-13.297 -7.417,-28.791 94.31,-28.791 160.274,-28.791 160.274,-13.297 -7.404,-13.297 -7.404,-28.791 32.614,-28.791 ; 55.194,-28.791 55.194,-13.297 ; 87.376,-18.462 87.376,-13.297 ; 108.712,-18.462 108.712,-13.297 ; 124.511,-28.956 124.511,-23.804
  text "COMPONENTS MARKED 'DNP' SHOULD NOT BE POPULATED." at 29.299,-8.09 h1.52
  text "ASSEMBLY VARIANT:" at 29.286,-11.024 h1.52
  text ".VariantName" at 55.601,-11.024 h1.52
  text "PCB VIEWED FROM TOP SIDE" at -5.804,-16.654 h1.52
  text "BOARD #:" at 57.099,-16.654 h1.52
  text ".PRJ_Number" at 70.955,-16.654 h1.52
  text "REV:" at 92.405,-16.654 h1.52
  text ".PCB_Rev" at 99.809,-16.654 h1.52
  text "SVN REV:" at 113.69,-16.654 h1.52
  text ".VersionControl_RevNumber" at 126.543,-16.654 h1.52
  text "TID #:" at 57.099,-21.819 h1.52
  text ".TID" at 70.955,-21.819 h1.52
  text "PLOT NAME =" at -5.804,-27.034 h1.52
  text ".plot_File_Name" at 14.656,-27.034 h1.52
  text "GENERATED    :" at 57.15,-27.034 h1.52
  text ".Print_Date" at 79.235,-27.034 h1.52
  text ".Print_Time" at 97.752,-27.034 h1.52
  text "TEXAS INSTRUMENTS" at 129.87,-27.034 h1.52
M6 Assembly Bottom:
  lines w0.254: -7.429,-18.474 160.261,-18.474 ; -7.379,-23.639 160.261,-23.639 ; 28.334,-28.969 28.334,-23.817 ; 44.133,-18.474 44.133,-13.31 ; 65.468,-18.474 65.468,-13.31 ; 97.65,-28.804 97.65,-13.31 ; 120.231,-28.804 160.249,-28.804 160.249,-13.31 -7.429,-13.31 -7.429,-28.804 58.534,-28.804 160.261,-28.804 160.261,-13.31
  text "COMPONENTS MARKED 'DNP' SHOULD NOT BE POPULATED." at 154.991,-8.077 h1.52
  text ".VariantName" at 128.473,-11.024 h1.52
  text "ASSEMBLY VARIANT:" at 154.864,-11.024 h1.52
  text ".VersionControl_RevNumber" at 26.302,-16.667 h1.52
  text "SVN REV:" at 39.154,-16.667 h1.52
  text ".PCB_Rev" at 53.035,-16.667 h1.52
  text "REV:" at 60.439,-16.667 h1.52
  text ".PRJ_Number" at 81.89,-16.667 h1.52
  text "BOARD #:" at 95.745,-16.667 h1.52
  text "PCB VIEWED FROM BOTTOM SIDE" at 158.648,-16.667 h1.52
  text ".TID" at 81.89,-21.831 h1.52
  text "TID #:" at 95.745,-21.831 h1.52
  text "TEXAS INSTRUMENTS" at 22.974,-27.047 h1.52
  text ".Print_Time" at 55.093,-27.047 h1.52
  text ".Print_Date" at 73.609,-27.047 h1.52
  text "GENERATED    :" at 95.694,-27.047 h1.52
  text ".plot_File_Name" at 138.189,-27.047 h1.52
  text "PLOT NAME =" at 158.648,-27.047 h1.52
M9 Title Sheet:
  drawing of 57 lines, arcs and shapes, not listed
  text "1" at 18.792,204.127 h1.78
  text "2" at 82.182,204.127 h1.78
  text "3" at 145.411,204.127 h1.78
  text "4" at 209.08,204.127 h1.78
  text "5" at 272.555,204.127 h1.78
  text "6" at 336.182,204.127 h1.78
  text "A" at -10.579,175.095 h1.78
  text "A" at 365.341,175.095 h1.78
  text "B" at -10.579,114.643 h1.78
  text "B" at 365.341,114.643 h1.78
  text "C" at -10.579,54.318 h1.78
  text "C" at 365.341,54.318 h1.78
  text "PROJECT TITLE:" at 288.125,7.048 h1.14
  text ".PRJ_Title" at 289.395,3.662 h1.78
  text "DESIGNED FOR:" at 288.125,-0.597 h1.14
  text ".PRJ_Customer" at 289.395,-4.153 h1.78
  text "D" at -10.579,-5.88 h1.78
  text "D" at 365.341,-5.88 h1.78
  text "FILE NAME:" at 288.125,-8.217 h1.14
  text ".PCB_File_Name_No_Path" at 289.395,-11.265 h1.78
  text "Texas Instruments (TI) and/or its licensors do not warrant the accuracy or completeness of this specification" at 161.9,-15.376 h1.14
  text "ENGINEER:" at 288.125,-15.583 h1.14
  text "LAYOUT BY:" at 326.352,-15.583 h1.14
  text "or any information contained therein. TI and/or its licensors do not warrant that this design will meet" at 160.757,-18.237 h1.14
  text ".PRJ_Engineer" at 289.395,-19.52 h1.78
  text ".PCB_Layout" at 327.635,-19.52 h1.78
  text "the specifications, will be suitable for your application or fit for any particular purpose, or will operate in" at 160.757,-21.099 h1.14
  text ".Layer_Name" at 14.656,-21.806 h1.52
  text "ALTIUM DESIGNER VERSION:" at 326.352,-23.457 h1.14
  text "an implementation. TI and/or its licensors do not warrant that the design is production worthy. You should" at 160.757,-23.961 h1.14
  text "completely validate and test your design implementation to confirm the system functionality for your application." at 161.9,-26.822 h1.14
  text ".print_Scale" at 289.395,-26.843 h1.78
  text ".Application_BuildNumber" at 327.635,-26.843 h1.78
  text "1" at 18.792,-32.093 h1.78
  text "2" at 82.182,-32.093 h1.78
  text "3" at 145.411,-32.093 h1.78
  text "4" at 209.08,-32.093 h1.78
  text "5" at 272.555,-32.093 h1.78
  text "6" at 336.182,-32.093 h1.78
M10 Fab Notes:
  drawing of 189 lines, arcs and shapes, not listed
  text "DESIGN INFORMATION" at 314.503,161.447 h1.52
  text "MIN. TRACK WIDTH:" at 298.131,158.091 h1.52
  text "8" at 325.976,158.091 h1.52
  text "MIL" at 329.907,158.091 h1.52
  text "MIN. CLEARANCE:" at 298.131,154.938 h1.52
  text "0.2" at 324.452,154.938 h1.52
  text "mm" at 329.907,154.938 h1.52
  text "MIN. VIA PAD SIZE:" at 298.131,151.785 h1.52
  text "24" at 325.214,151.785 h1.52
  text "MIL" at 329.907,151.785 h1.52
  text "0.05mm (2MIL)" at 315.784,148.486 h1.52
  text "MINIMUM ANNULAR RING" at 289.769,148.277 h1.52
  text "EXTERNAL" at 333.768,148.277 h1.52
  text "PER" at 294.849,145.48 h1.52
  text "IPC-D-275 CLASS 2 LEVEL C" at 300.437,145.48 h1.52
  text "MIL, HOLES" at 338.238,142.928 h1.52
  text "+/-" at 328.27,142.709 h1.52
  text "+/-" at 349.961,142.709 h1.52
  text "REGISTRATION TOLERANCES:" at 289.769,142.682 h1.52
  text "METAL" at 320.243,142.682 h1.52
  text "5" at 334.879,142.683 h1.52
  text "3" at 356.037,142.683 h1.52
  text "MIL" at 358.99,142.682 h1.52
  text "HOLE SIZE TOLERANCE (UNLESS OTHERWISE SPECIFIED):" at 289.769,140.185 h1.52
  text "+/-" at 349.961,140.112 h1.52
  text "3" at 356.037,140.085 h1.52
  text "MIL" at 358.99,140.085 h1.52
  text "MATERIAL:" at 287.87,136.589 h1.52
  text "FR-4 High Tg" at 312.926,133.324 h1.52
  text "X" at 309.257,133.122 h1.52
  text "FR-408" at 298.563,133.007 h1.52
  text "OTHER" at 336.358,133.007 h1.52
  text "62 MIL (1.6mm) +/-10%" at 306.694,129.374 h1.52
  text "X" at 303.643,129.312 h1.52
  text "THICKNESS:" at 289.769,129.165 h1.52
  text "OTHER" at 339.33,129.165 h1.52
  text "TOLERANCE:" at 289.769,125.652 h1.52
  text "X" at 311.314,125.652 h1.52
  text "ANSI IPC-6012 TYPE 3 CLASS 2" at 315.836,125.652 h1.52
  text "OTHER +/-" at 315.835,121.989 h1.52
  text "BOW & TWIST:" at 289.769,118.302 h1.52
  text "X" at 311.314,118.302 h1.52
  text "ANSI IPC-6012 TYPE 3 CLASS 2" at 315.836,118.302 h1.52
  text "OTHER +/-" at 315.835,114.576 h1.52
  text "DRILLING:" at 287.87,111.258 h1.52
  text "NC_DRILL FILES" at 332.599,108.586 h1.52
  text "REFERENCE:" at 289.769,108.486 h1.52
  text "X" at 306.463,108.484 h1.52
  text "AS SHOWN" at 310.984,108.486 h1.52
  text "X" at 329.348,108.486 h1.52
  text "OTHER" at 340.168,104.873 h1.52
  text "PTH COPPER THICKNESS:" at 289.761,104.783 h1.52
  text "X" at 318.697,104.783 h1.52
  text "20-30 um" at 321.948,104.783 h1.52
  text "BOARD FINISH:" at 287.87,101.034 h1.52
  text "SILKSCREEN:" at 291.812,98.237 h1.52
  text "X" at 316.14,98.237 h1.52
  text "TOP" at 319.112,98.237 h1.52
  text "X" at 329.094,98.237 h1.52
  text "BOTTOM" at 332.091,98.237 h1.52
  text "SILKSCREEN COLOR:" at 291.812,94.295 h1.52
  text "X" at 316.115,94.295 h1.52
  text "WHITE" at 319.112,94.295 h1.52
  text "OTHER" at 332.091,94.295 h1.52
  text "X" at 319.442,90.652 h1.52
  text "GREEN" at 322.439,90.652 h1.52
  text "OTHER" at 338.136,90.652 h1.52
  text "SOLDER RESIST COLOR:" at 291.812,90.477 h1.52
  text "X" at 319.442,86.734 h1.52
  text "MATTE" at 322.439,86.734 h1.52
  text "SEMI-GLOSS" at 338.125,86.717 h1.52
  text "IMMERSION GOLD (ENIG)" at 314.819,82.345 h1.52
  text "ENEPIG" at 348.793,82.162 h1.52
  text "SURFACE FINISH:" at 287.87,82.136 h1.52
  text "X" at 310.298,82.136 h1.52
  text "IMM. TIN/SILVER OR EQUIV" at 296.24,78.649 h1.52
  text "OTHER" at 332.599,78.549 h1.52
  text "ARRAY/PANEL:" at 287.87,74.602 h1.52
  text "CUT AND TRIM PER M1 BOARD OUTLINE" at 314.819,74.393 h1.52
  text "N.C. ROUTE" at 314.819,70.94 h1.52
  text "X" at 332.295,70.94 h1.52
  text "V. SCORE" at 336.816,70.94 h1.52
  text "CERTIFICATION:" at 287.87,67.66 h1.52
  text "MATERIALS AND WORKMANSHIP FOR ALL PCBS" at 306.285,67.66 h1.52
  text "TO MEET OR EXCEED THE REQUIREMENTS OF:" at 306.285,65.271 h1.52
  text "X" at 297.078,62.003 h1.52
  text "ANSI IPC-A-600F CLASS ->" at 300.329,62.003 h1.52
  text "X" at 342.188,62.003 h1.52
  text "2" at 344.982,62.003 h1.52
  text "1" at 336.981,61.965 h1.52
  text "3" at 353.973,61.965 h1.52
  text "X" at 317.702,58.252 h1.52
  text "RoHS" at 320.953,58.252 h1.52
  text "OTHER" at 337.321,58.252 h1.52
  text "PER ORDER" at 347.407,58.252 h1.52
  text "ALL BOARDS MUST MEET OR EXCEED UL94-V0 REQUIREMENTS." at 288.569,54.345 h1.52
  text "PCB MUST BEAR THE UL94V-0 UL REGISTERED MATERIAL ID NUMBER" at 288.569,51.397 h1.52
  text "ADDITIONAL REQUIREMENTS:" at 287.87,47.094 h1.52
  text "MICROSECTION:" at 289.769,44.373 h1.52
  text "YES" at 312.775,44.373 h1.52
  text "REQUIRED" at 334.657,40.707 h1.52
  text "BARE BOARD ELEC. TEST:" at 289.769,40.634 h1.52
  text "NONE" at 322.935,40.634 h1.52
  text "X" at 331.66,40.634 h1.52
  text "PER ORDER" at 349.693,40.634 h1.52
  text "XX MIL VIAS REQUIRE NON-CONDUCTIVE FILL AND PLANARIZE" at 294.04,35.428 h1.5
  text "XX MIL VIAS REQUIRE CONDUCTIVE FILL AND PLANARIZE" at 294.243,32.787 h1.52
  text "OUTER XX MIL TRACES REQUIRE 50 OHM SINGLE-ENDED IMPEDANCE" at 294.218,28.637 h1.47
  text "LAYER 2 & 3 (INNER LAYERS) XX MIL WIDE, XX MIL SPACE / TRACES REQUIRE 100 OHM DIFFERENTIAL IMPEDANCE" at 294.015,22.65 h1.52
  text ".Layer_Name" at 14.656,-21.806 h1.52
M11 Gerber Information:
  lines w0.254: -7.417,-23.626 160.223,-23.626 ; -7.417,-18.462 160.274,-18.462 ; -7.417,-13.297 -7.417,-28.791 94.31,-28.791 160.274,-28.791 160.274,-13.297 -7.404,-13.297 -7.404,-28.791 32.614,-28.791 ; 55.194,-28.791 55.194,-13.297 ; 87.376,-18.462 87.376,-13.297 ; 108.712,-18.462 108.712,-13.297 ; 124.511,-28.956 124.511,-23.804
  text "ALL ARTWORK VIEWED FROM TOP SIDE" at -5.804,-16.654 h1.52
  text "BOARD #:" at 57.099,-16.654 h1.52
  text ".PRJ_Number" at 70.955,-16.654 h1.52
  text "REV:" at 92.405,-16.654 h1.52
  text ".PCB_Rev" at 99.809,-16.654 h1.52
  text "SVN REV:" at 113.69,-16.654 h1.52
  text ".VersionControl_RevNumber" at 126.543,-16.654 h1.52
  text "LAYER NAME =" at -5.804,-21.806 h1.52
  text "TID #:" at 57.099,-21.819 h1.52
  text ".TID" at 70.955,-21.819 h1.52
  text "PLOT NAME =" at -5.804,-27.034 h1.52
  text ".plot_File_Name" at 14.656,-27.034 h1.52
  text "GENERATED    :" at 57.15,-27.034 h1.52
  text ".Print_Date" at 79.235,-27.034 h1.52
  text ".Print_Time" at 97.752,-27.034 h1.52
  text "TEXAS INSTRUMENTS" at 129.87,-27.034 h1.52
M12 Stackup:
  drawing of 191 lines, arcs and shapes, not listed
  text "Layer" at 248.865,194.881 h1.52
  text "Name" at 259.277,194.881 h1.52
  text "Material" at 282.892,194.881 h1.52
  text "Thickness" at 304.731,194.881 h1.52
  text "Constant" at 321.236,194.881 h1.52
  text "Board Layer Stack" at 335.711,194.881 h1.52
  text "1" at 248.865,191.833 h1.52
  text "Top Overlay" at 259.277,191.833 h1.52
  text "2" at 248.865,188.785 h1.52
  text "Top Solder" at 259.277,188.785 h1.52
  text "Solder Resist" at 282.892,188.785 h1.52
  text "0.40mil" at 304.731,188.785 h1.52
  text "3.5" at 321.236,188.785 h1.52
  text "3" at 248.865,185.737 h1.52
  text "Top Layer" at 259.277,185.737 h1.52
  text "Copper" at 282.892,185.737 h1.52
  text "1.40mil" at 304.731,185.737 h1.52
  text "4" at 248.865,182.689 h1.52
  text "Dielectric1" at 259.277,182.689 h1.52
  text "FR-4" at 282.892,182.689 h1.52
  text "59.20mil" at 304.731,182.689 h1.52
  text "4.8" at 321.236,182.689 h1.52
  text "5" at 248.865,179.641 h1.52
  text "Bottom Layer" at 259.277,179.641 h1.52
  text "Copper" at 282.892,179.641 h1.52
  text "1.40mil" at 304.731,179.641 h1.52
  text "6" at 248.865,176.594 h1.52
  text "Bottom Solder" at 259.277,176.594 h1.52
  text "Solder Resist" at 282.892,176.594 h1.52
  text "0.40mil" at 304.731,176.594 h1.52
  text "3.5" at 321.236,176.594 h1.52
  text "7" at 248.865,173.546 h1.52
  text "Bottom Overlay" at 259.277,173.546 h1.52
  text ".Layer_Name" at 14.656,-21.806 h1.52
M13 Component Bodies Top:
  text ".Layer_Name" at 14.656,-21.806 h1.52
M14 Component Bodies Bottom:
  text ".Layer_Name" at 14.656,-21.806 h1.52
M15 Courtyards Top:
  text ".Layer_Name" at 14.656,-21.806 h1.52
M16 Courtyards Bottom:
  text ".Layer_Name" at 14.656,-21.806 h1.52
Drill Drawing:
  circle w0.254: c136.237,74.87 r0.701
  lines w0.254: 135.536,77.324 136.939,77.324 136.939,78.727 135.536,78.727 135.536,77.324 ; 135.536,80.831 135.887,80.831 136.237,80.48 136.588,80.831 136.939,80.831 136.588,81.182 136.939,81.532 136.588,81.532 136.237,81.883 135.887,81.532 135.536,81.532 135.887,81.182 135.536,80.831 ; 135.536,85.039 136.939,85.039 136.237,83.636 135.536,85.039
  lines w0.305: 134.264,73.221 216.35,73.221 ; 134.264,85.846 216.35,85.846 ; 142.847,70.065 142.847,89.002 ; 151.283,70.065 151.283,89.002 ; 167.459,70.065 167.459,89.002 ; 174.043,70.065 174.043,89.002 ; 183.576,70.065 183.576,89.002 ; 201.957,70.065 201.957,89.002 ; 134.264,70.065 216.35,70.065 216.35,89.002 134.264,89.002 134.264,70.065
  text "Symbol" at 136.158,86.792 h1.83
  text "Quantity" at 143.793,86.792 h1.83
  text "Finished Hole Size" at 152.23,86.792 h1.83
  text "Plated" at 168.406,86.792 h1.83
  text "Hole Type" at 174.99,86.792 h1.83
  text "Drill Layer Pair" at 184.522,86.792 h1.83
  text "Hole Tolerance" at 202.904,86.792 h1.83
  text "8" at 143.793,83.636 h1.52
  text "7.87mil (0.200mm)" at 152.23,83.636 h1.52
  text "PTH" at 168.406,83.636 h1.52
  text "Round" at 174.99,83.636 h1.52
  text "Top Layer - Bottom Layer" at 184.522,83.636 h1.52
  text "56" at 143.793,80.48 h1.52
  text "11.81mil (0.300mm)" at 152.23,80.48 h1.52
  text "PTH" at 168.406,80.48 h1.52
  text "Round" at 174.99,80.48 h1.52
  text "Top Layer - Bottom Layer" at 184.522,80.48 h1.52
  text "12" at 143.793,77.324 h1.52
  text "43.31mil (1.100mm)" at 152.23,77.324 h1.52
  text "PTH" at 168.406,77.324 h1.52
  text "Round" at 174.99,77.324 h1.52
  text "Top Layer - Bottom Layer" at 184.522,77.324 h1.52
  text "4" at 143.793,74.168 h1.52
  text "125.98mil (3.200mm)" at 152.23,74.168 h1.52
  text "PTH" at 168.406,74.168 h1.52
  text "Round" at 174.99,74.168 h1.52
  text "Top Layer - Bottom Layer" at 184.522,74.168 h1.52
  text "80 Total" at 143.793,71.012 h1.52
  text ".Layer_Name" at 14.656,-21.806 h1.52
M17 Embedded Cavity:
  text ".Layer_Name" at 14.656,-21.806 h1.52
M18 Embedded Assembly:
  text ".Layer_Name" at 14.656,-21.806 h1.52
M19 Embedded Keepout:
  text ".Layer_Name" at 14.656,-21.806 h1.52

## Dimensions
0,-10.16 to 25.4,-10.16 on M2 Board Dimensions
0,0 to 0,40 on M2 Board Dimensions
0,0 to 60,0 on M2 Board Dimensions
